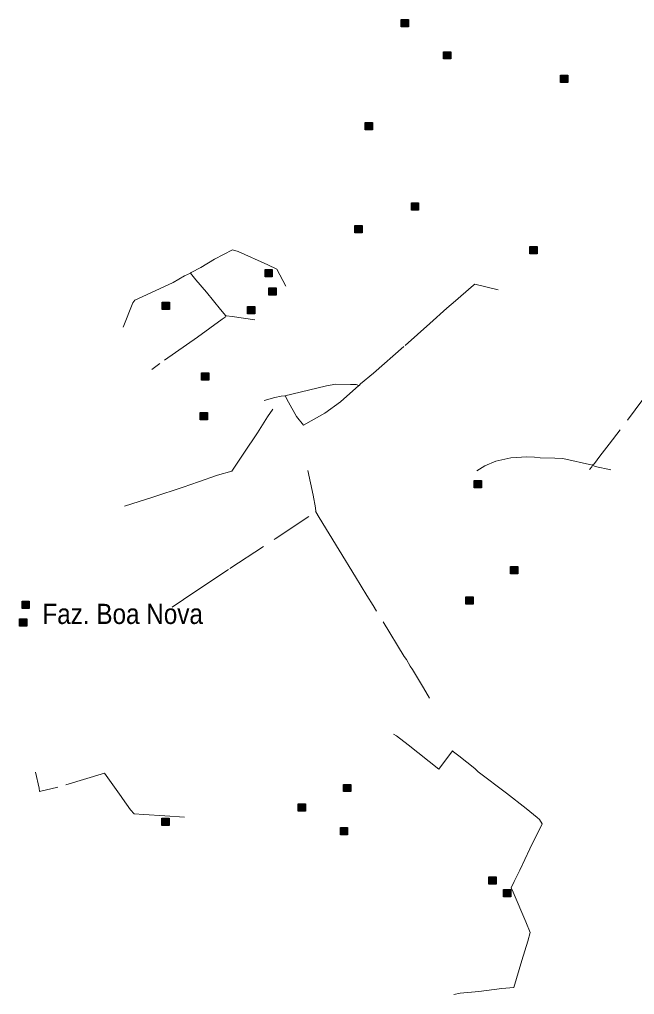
# Model space of a CAD drawing. Extents: x 393.5 to 446.9, y 8064.8 to 8120.4.
# Drawn here: x 405.3 to 410.18, y 8111.87 to 8119.6 of the extents above; entities that cross this region are included whole.
import ezdxf

# ---------------------------------------------------------------- set-up
doc = ezdxf.new("R2010")
doc.units = 0
doc.header["$LTSCALE"] = 0.064
doc.linetypes.add('DOT_DASHED', pattern=[7.7, 5, -1.2, 0.3, -1.2])
doc.layers.add('2', color=7, linetype='Continuous', lineweight=25)
doc.layers.add('22', color=7, linetype='DOT_DASHED', lineweight=13)
doc.layers.add('61', color=7, linetype='Continuous')

msp = doc.modelspace()

# ---------------------------------------------------------------- hatches: boundary and pattern name
at = {"layer": '2'}
for points in [[(408.3334, 8119.5997), (408.3914, 8119.5997), (408.3914, 8119.5417), (408.3334, 8119.5417)], [(408.6681, 8119.3446), (408.7261, 8119.3446), (408.7261, 8119.2866), (408.6681, 8119.2866)], [(409.5973, 8119.1576), (409.6553, 8119.1576), (409.6553, 8119.0996), (409.5973, 8119.0996)], [(408.0481, 8118.7823), (408.1061, 8118.7823), (408.1061, 8118.7243), (408.0481, 8118.7243)], [(408.4132, 8118.1458), (408.4712, 8118.1458), (408.4712, 8118.0878), (408.4132, 8118.0878)], [(407.965, 8117.9672), (408.023, 8117.9672), (408.023, 8117.9092), (407.965, 8117.9092)], [(409.3525, 8117.7989), (409.4105, 8117.7989), (409.4105, 8117.7409), (409.3525, 8117.7409)], [(407.2522, 8117.6176), (407.3102, 8117.6176), (407.3102, 8117.5596), (407.2522, 8117.5596)], [(407.2827, 8117.4717), (407.3407, 8117.4717), (407.3407, 8117.4137), (407.2827, 8117.4137)], [(406.4354, 8117.3575), (406.4934, 8117.3575), (406.4934, 8117.2995), (406.4354, 8117.2995)], [(407.1122, 8117.3236), (407.1702, 8117.3236), (407.1702, 8117.2656), (407.1122, 8117.2656)], [(406.7485, 8116.7986), (406.8065, 8116.7986), (406.8065, 8116.7406), (406.7485, 8116.7406)], [(406.7376, 8116.4822), (406.7956, 8116.4822), (406.7956, 8116.4242), (406.7376, 8116.4242)], [(408.911, 8115.9443), (408.969, 8115.9443), (408.969, 8115.8863), (408.911, 8115.8863)], [(409.2009, 8115.2615), (409.2589, 8115.2615), (409.2589, 8115.2035), (409.2009, 8115.2035)], [(405.3243, 8114.9881), (405.3823, 8114.9881), (405.3823, 8114.9301), (405.3243, 8114.9301)], [(408.8457, 8115.0223), (408.9037, 8115.0223), (408.9037, 8114.9643), (408.8457, 8114.9643)], [(405.3043, 8114.8467), (405.3623, 8114.8467), (405.3623, 8114.7887), (405.3043, 8114.7887)], [(407.8759, 8113.535), (407.9339, 8113.535), (407.9339, 8113.477), (407.8759, 8113.477)], [(407.515, 8113.3807), (407.573, 8113.3807), (407.573, 8113.3227), (407.515, 8113.3227)], [(406.4337, 8113.2659), (406.4917, 8113.2659), (406.4917, 8113.2079), (406.4337, 8113.2079)], [(407.8498, 8113.1919), (407.9078, 8113.1919), (407.9078, 8113.1339), (407.8498, 8113.1339)], [(409.0289, 8112.8014), (409.0869, 8112.8014), (409.0869, 8112.7434), (409.0289, 8112.7434)], [(409.145, 8112.7003), (409.203, 8112.7003), (409.203, 8112.6423), (409.145, 8112.6423)]]:
    msp.add_hatch(color=256, dxfattribs=at).paths.add_polyline_path(points)

# ---------------------------------------------------------------- linework, layer by layer
for points in [[(408.3334, 8119.5997), (408.3914, 8119.5997), (408.3914, 8119.5417), (408.3334, 8119.5417)], [(408.6681, 8119.3446), (408.7261, 8119.3446), (408.7261, 8119.2866), (408.6681, 8119.2866)], [(409.5973, 8119.1576), (409.6553, 8119.1576), (409.6553, 8119.0996), (409.5973, 8119.0996)], [(408.0481, 8118.7823), (408.1061, 8118.7823), (408.1061, 8118.7243), (408.0481, 8118.7243)], [(408.4132, 8118.1458), (408.4712, 8118.1458), (408.4712, 8118.0878), (408.4132, 8118.0878)], [(407.965, 8117.9672), (408.023, 8117.9672), (408.023, 8117.9092), (407.965, 8117.9092)], [(409.3525, 8117.7989), (409.4105, 8117.7989), (409.4105, 8117.7409), (409.3525, 8117.7409)], [(407.2522, 8117.6176), (407.3102, 8117.6176), (407.3102, 8117.5596), (407.2522, 8117.5596)], [(407.2827, 8117.4717), (407.3407, 8117.4717), (407.3407, 8117.4137), (407.2827, 8117.4137)], [(406.4354, 8117.3575), (406.4934, 8117.3575), (406.4934, 8117.2995), (406.4354, 8117.2995)], [(407.1122, 8117.3236), (407.1702, 8117.3236), (407.1702, 8117.2656), (407.1122, 8117.2656)], [(406.7485, 8116.7986), (406.8065, 8116.7986), (406.8065, 8116.7406), (406.7485, 8116.7406)], [(406.7376, 8116.4822), (406.7956, 8116.4822), (406.7956, 8116.4242), (406.7376, 8116.4242)], [(408.911, 8115.9443), (408.969, 8115.9443), (408.969, 8115.8863), (408.911, 8115.8863)], [(409.2009, 8115.2615), (409.2589, 8115.2615), (409.2589, 8115.2035), (409.2009, 8115.2035)], [(405.3243, 8114.9881), (405.3823, 8114.9881), (405.3823, 8114.9301), (405.3243, 8114.9301)], [(408.8457, 8115.0223), (408.9037, 8115.0223), (408.9037, 8114.9643), (408.8457, 8114.9643)], [(405.3043, 8114.8467), (405.3623, 8114.8467), (405.3623, 8114.7887), (405.3043, 8114.7887)], [(407.8759, 8113.535), (407.9339, 8113.535), (407.9339, 8113.477), (407.8759, 8113.477)], [(407.515, 8113.3807), (407.573, 8113.3807), (407.573, 8113.3227), (407.515, 8113.3227)], [(406.4337, 8113.2659), (406.4917, 8113.2659), (406.4917, 8113.2079), (406.4337, 8113.2079)], [(407.8498, 8113.1919), (407.9078, 8113.1919), (407.9078, 8113.1339), (407.8498, 8113.1339)], [(409.0289, 8112.8014), (409.0869, 8112.8014), (409.0869, 8112.7434), (409.0289, 8112.7434)], [(409.145, 8112.7003), (409.203, 8112.7003), (409.203, 8112.6423), (409.145, 8112.6423)]]:
    msp.add_lwpolyline(points, close=True, dxfattribs=at)
at = {"layer": '22'}
for points in [[(406.667, 8117.5923), (406.7432, 8117.6345), (406.8509, 8117.6984), (406.9949, 8117.774), (407.0385, 8117.7609), (407.2751, 8117.6536), (407.3449, 8117.6202), (407.4177, 8117.4865)], [(406.1262, 8117.159), (406.2033, 8117.3523), (406.2193, 8117.3755), (406.3458, 8117.4322), (406.5236, 8117.5153), (406.6123, 8117.5676), (406.6618, 8117.5894), (406.667, 8117.5923)], [(406.6618, 8117.5894), (406.7033, 8117.5356), (406.7876, 8117.4368), (406.8982, 8117.3002), (406.9423, 8117.2499)], [(408.0108, 8116.7112), (408.1119, 8116.7963), (408.3635, 8117.0159), (408.5596, 8117.1888), (408.696, 8117.3098), (408.7634, 8117.3695), (408.805, 8117.4052), (408.9066, 8117.4943), (408.9158, 8117.5019), (409.1027, 8117.456)], [(406.935, 8117.2383), (406.9118, 8117.2237), (406.7176, 8117.0816), (406.4168, 8116.8712), (406.3538, 8116.825)], [(407.1707, 8117.2194), (406.9903, 8117.2441), (406.9455, 8117.2495), (406.9423, 8117.2499), (406.935, 8117.2383)], [(410.7672, 8117.1408), (410.7528, 8117.1278), (410.5387, 8116.9665), (410.4972, 8116.912), (410.3175, 8116.6797), (410.071, 8116.3467), (409.9837, 8116.2312), (409.9078, 8116.1376), (409.8671, 8116.0796), (409.8512, 8116.0652), (409.8511, 8116.0651)], [(407.4105, 8116.6145), (407.4655, 8116.6299), (407.739, 8116.6938), (407.8141, 8116.7091), (407.9305, 8116.7045), (407.9765, 8116.7045), (407.9969, 8116.6987), (407.9979, 8116.6984), (408.0108, 8116.7112)], [(407.4134, 8116.6146), (407.4387, 8116.5641), (407.5015, 8116.4524), (407.5582, 8116.3819), (407.618, 8116.4187), (407.7268, 8116.4784), (407.8508, 8116.5687), (407.9963, 8116.697), (407.9979, 8116.6984)], [(407.2464, 8116.5778), (407.3292, 8116.6023), (407.3797, 8116.613), (407.4105, 8116.6145), (407.4134, 8116.6146)], [(406.1361, 8115.7402), (406.3629, 8115.8121), (406.6034, 8115.8917), (406.7244, 8115.9346), (406.8753, 8115.9875), (406.9886, 8116.0181), (407.0836, 8116.1605), (407.1924, 8116.3212), (407.2721, 8116.4498), (407.315, 8116.511)], [(408.9324, 8116.0197), (408.9951, 8116.061), (409.0822, 8116.0987), (409.2014, 8116.1249), (409.3285, 8116.1307), (409.3909, 8116.1292), (409.436, 8116.1248), (409.5509, 8116.121)], [(409.5509, 8116.121), (409.6161, 8116.1176), (409.8511, 8116.0651)], [(409.8253, 8116.0305), (409.8442, 8116.0537), (409.8506, 8116.0643), (409.8508, 8116.0647), (409.8511, 8116.0651)], [(409.9953, 8116.028), (409.8714, 8116.0549), (409.8511, 8116.0651)], [(407.6527, 8115.7276), (407.6336, 8115.829), (407.5914, 8116.0233)], [(406.5154, 8114.9411), (406.6945, 8115.0623), (406.9738, 8115.2455), (407.3321, 8115.4826), (407.6518, 8115.6931), (407.6552, 8115.6954), (407.6566, 8115.6963), (407.6564, 8115.6978), (407.6527, 8115.7276)], [(408.4047, 8114.471), (408.3743, 8114.5239), (408.3552, 8114.5492), (408.1091, 8114.9537), (408.0598, 8115.0318), (407.9689, 8115.1796), (407.8406, 8115.3907), (407.6813, 8115.651), (407.6566, 8115.6963)], [(408.5575, 8114.2184), (408.5093, 8114.3005), (408.4227, 8114.4462), (408.4047, 8114.471)], [(408.7899, 8113.7618), (408.7477, 8113.7934), (408.7384, 8113.7994), (408.6319, 8113.6552), (408.3875, 8113.8472), (408.2945, 8113.9186), (408.2705, 8113.9337)], [(409.4106, 8113.2734), (409.3244, 8113.343), (409.1675, 8113.4638), (408.944, 8113.6335), (408.9174, 8113.6619), (408.7899, 8113.7618)], [(406.112, 8113.4398), (405.9781, 8113.6246), (405.609, 8113.5119), (405.4635, 8113.477), (405.4608, 8113.5038), (405.4304, 8113.6312)], [(406.6142, 8113.275), (406.4567, 8113.2856), (406.2916, 8113.2962), (406.2129, 8113.3008), (406.1841, 8113.3341), (406.122, 8113.4233), (406.112, 8113.4398)], [(408.7499, 8111.8686), (408.8006, 8111.8792), (408.948, 8111.8934), (409.1309, 8111.9165), (409.2268, 8111.9236), (409.289, 8112.1383), (409.3369, 8112.2928), (409.3547, 8112.3602), (409.321, 8112.4454), (409.2206, 8112.6797), (409.2064, 8112.7134), (409.2295, 8112.7649), (409.273, 8112.8554), (409.3529, 8113.024), (409.4515, 8113.2209), (409.4302, 8113.2564), (409.4106, 8113.2734)]]:
    msp.add_lwpolyline(points, dxfattribs=at)

# ---------------------------------------------------------------- texts
at = {"layer": '61', "width": 0.9}
msp.add_text('Faz. Boa Nova', height=0.16, dxfattribs=at).set_placement((405.4861, 8114.8066))

doc.saveas('drawing.dxf')
